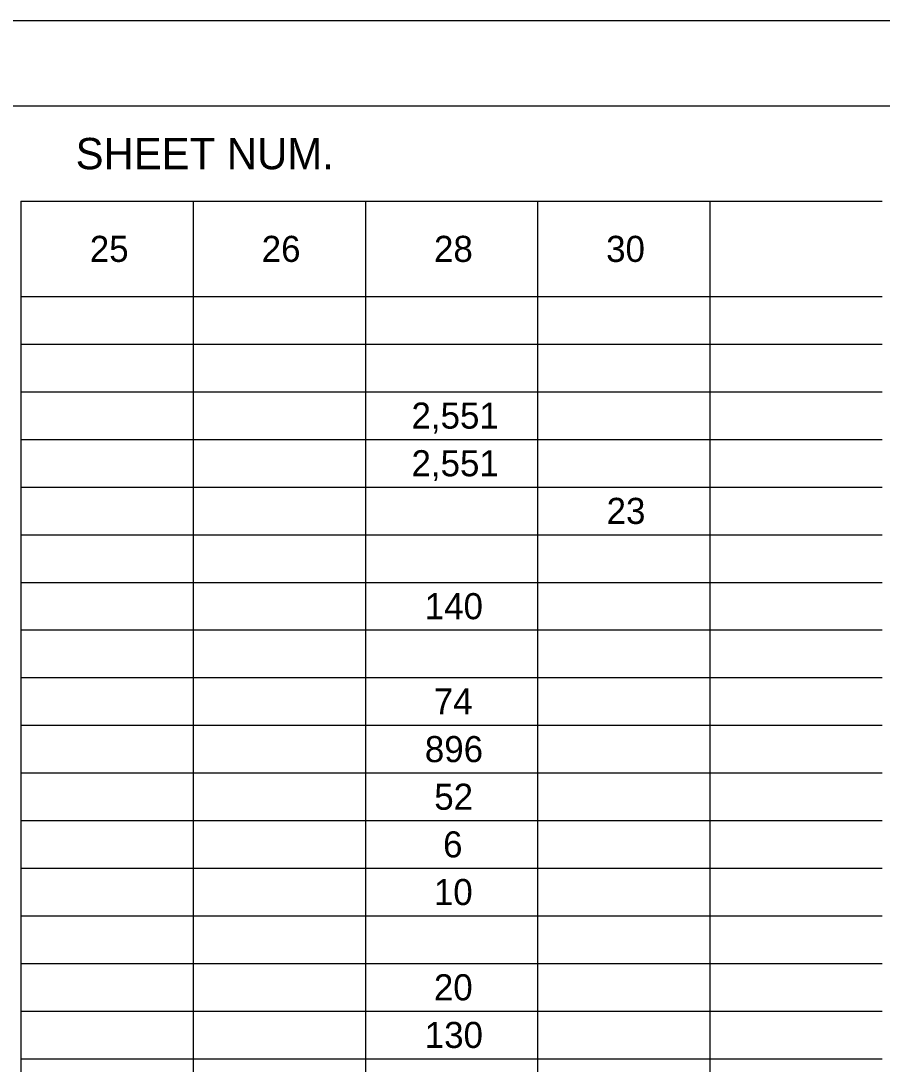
# Model space of a CAD drawing. Extents: x 0 to 34, y 0 to 22.
# Drawn here: x 4.54 to 9.6, y 15.87 to 22 of the extents above; entities that cross this region are included whole.
import ezdxf

# ---------------------------------------------------------------- set-up
doc = ezdxf.new("R2010")
doc.units = 0
for name, color, linetype in [('SH_Border', 7, 'Continuous'), ('SH_Cut_Line', 7, 'Continuous'), ('SH_Text', 7, 'Continuous')]:
    doc.layers.add(name, color=color, linetype=linetype)

msp = doc.modelspace()

# ---------------------------------------------------------------- linework, layer by layer
at = {"layer": 'SH_Border'}
msp.add_lwpolyline([(1.5, 21.5), (33.5, 21.5), (33.5, 0.5), (1.5, 0.5)], close=True, dxfattribs=at)
at = {"layer": 'SH_Cut_Line'}
msp.add_lwpolyline([(0, 0), (34, 0), (34, 22), (0, 22)], close=True, dxfattribs=at)
at = {"layer": 'SH_Text'}
for p, q in [((4.537, 21.5), (5.5494, 21.5)), ((5.5494, 21.5), (6.5617, 21.5)), ((6.5617, 21.5), (7.574, 21.5)), ((7.574, 21.5), (8.5864, 21.5)), ((8.5864, 21.5), (9.5987, 21.5)), ((4.537, 20.94), (5.5494, 20.94)), ((4.537, 20.94), (4.537, 20.66)), ((5.5494, 20.94), (6.5617, 20.94)), ((5.5494, 20.94), (5.5494, 20.66)), ((6.5617, 20.94), (7.574, 20.94)), ((6.5617, 20.94), (6.5617, 20.66)), ((7.574, 20.94), (8.5864, 20.94)), ((7.574, 20.94), (7.574, 20.66)), ((8.5864, 20.94), (9.5987, 20.94)), ((8.5864, 20.94), (8.5864, 20.66)), ((4.537, 20.66), (4.537, 20.38)), ((5.5494, 20.66), (5.5494, 20.38)), ((6.5617, 20.66), (6.5617, 20.38)), ((7.574, 20.66), (7.574, 20.38)), ((8.5864, 20.66), (8.5864, 20.38)), ((4.537, 20.38), (5.5494, 20.38)), ((4.537, 20.38), (4.537, 20.1)), ((5.5494, 20.38), (6.5617, 20.38)), ((5.5494, 20.38), (5.5494, 20.1)), ((6.5617, 20.38), (7.574, 20.38)), ((6.5617, 20.38), (6.5617, 20.1)), ((7.574, 20.38), (8.5864, 20.38)), ((7.574, 20.38), (7.574, 20.1)), ((8.5864, 20.38), (9.5987, 20.38)), ((8.5864, 20.38), (8.5864, 20.1)), ((4.537, 20.1), (5.5494, 20.1)), ((4.537, 20.1), (4.537, 18.7)), ((5.5494, 20.1), (6.5617, 20.1)), ((5.5494, 20.1), (5.5494, 18.7)), ((6.5617, 20.1), (7.574, 20.1)), ((6.5617, 20.1), (6.5617, 18.7)), ((7.574, 20.1), (8.5864, 20.1)), ((7.574, 20.1), (7.574, 18.7)), ((8.5864, 20.1), (9.5987, 20.1)), ((8.5864, 20.1), (8.5864, 18.7)), ((4.537, 19.82), (5.5494, 19.82)), ((5.5494, 19.82), (6.5617, 19.82)), ((6.5617, 19.82), (7.574, 19.82)), ((7.574, 19.82), (8.5864, 19.82)), ((8.5864, 19.82), (9.5987, 19.82)), ((4.537, 19.54), (5.5494, 19.54)), ((5.5494, 19.54), (6.5617, 19.54)), ((6.5617, 19.54), (7.574, 19.54)), ((7.574, 19.54), (8.5864, 19.54)), ((8.5864, 19.54), (9.5987, 19.54)), ((4.537, 19.26), (5.5494, 19.26)), ((5.5494, 19.26), (6.5617, 19.26)), ((6.5617, 19.26), (7.574, 19.26)), ((7.574, 19.26), (8.5864, 19.26)), ((8.5864, 19.26), (9.5987, 19.26)), ((4.537, 18.98), (5.5494, 18.98)), ((5.5494, 18.98), (6.5617, 18.98)), ((6.5617, 18.98), (7.574, 18.98)), ((7.574, 18.98), (8.5864, 18.98)), ((8.5864, 18.98), (9.5987, 18.98)), ((4.537, 18.7), (5.5494, 18.7)), ((4.537, 18.7), (4.537, 18.14)), ((5.5494, 18.7), (6.5617, 18.7)), ((5.5494, 18.7), (5.5494, 18.14)), ((6.5617, 18.7), (7.574, 18.7)), ((6.5617, 18.7), (6.5617, 18.14)), ((7.574, 18.7), (8.5864, 18.7)), ((7.574, 18.7), (7.574, 18.14)), ((8.5864, 18.7), (9.5987, 18.7)), ((8.5864, 18.7), (8.5864, 18.14)), ((4.537, 18.42), (5.5494, 18.42)), ((5.5494, 18.42), (6.5617, 18.42)), ((6.5617, 18.42), (7.574, 18.42)), ((7.574, 18.42), (8.5864, 18.42)), ((8.5864, 18.42), (9.5987, 18.42)), ((4.537, 18.14), (5.5494, 18.14)), ((4.537, 18.14), (4.537, 17.86)), ((5.5494, 18.14), (6.5617, 18.14)), ((5.5494, 18.14), (5.5494, 17.86)), ((6.5617, 18.14), (7.574, 18.14)), ((6.5617, 18.14), (6.5617, 17.86)), ((7.574, 18.14), (8.5864, 18.14)), ((7.574, 18.14), (7.574, 17.86)), ((8.5864, 18.14), (9.5987, 18.14)), ((8.5864, 18.14), (8.5864, 17.86)), ((4.537, 17.86), (5.5494, 17.86)), ((4.537, 17.86), (4.537, 17.58)), ((5.5494, 17.86), (6.5617, 17.86)), ((5.5494, 17.86), (5.5494, 17.58)), ((6.5617, 17.86), (7.574, 17.86)), ((6.5617, 17.86), (6.5617, 17.58)), ((7.574, 17.86), (8.5864, 17.86)), ((7.574, 17.86), (7.574, 17.58)), ((8.5864, 17.86), (9.5987, 17.86)), ((8.5864, 17.86), (8.5864, 17.58)), ((4.537, 17.58), (5.5494, 17.58)), ((4.537, 17.58), (4.537, 17.3)), ((5.5494, 17.58), (6.5617, 17.58)), ((5.5494, 17.58), (5.5494, 17.3)), ((6.5617, 17.58), (7.574, 17.58)), ((6.5617, 17.58), (6.5617, 17.3)), ((7.574, 17.58), (8.5864, 17.58)), ((7.574, 17.58), (7.574, 17.3)), ((8.5864, 17.58), (9.5987, 17.58)), ((8.5864, 17.58), (8.5864, 17.3)), ((4.537, 17.3), (5.5494, 17.3)), ((4.537, 17.3), (4.537, 17.02)), ((5.5494, 17.3), (6.5617, 17.3)), ((5.5494, 17.3), (5.5494, 17.02)), ((6.5617, 17.3), (7.574, 17.3)), ((6.5617, 17.3), (6.5617, 17.02)), ((7.574, 17.3), (8.5864, 17.3)), ((7.574, 17.3), (7.574, 17.02)), ((8.5864, 17.3), (9.5987, 17.3)), ((8.5864, 17.3), (8.5864, 17.02)), ((4.537, 17.02), (5.5494, 17.02)), ((4.537, 17.02), (4.537, 16.74)), ((5.5494, 17.02), (6.5617, 17.02)), ((5.5494, 17.02), (5.5494, 16.74)), ((6.5617, 17.02), (7.574, 17.02)), ((6.5617, 17.02), (6.5617, 16.74)), ((7.574, 17.02), (8.5864, 17.02)), ((7.574, 17.02), (7.574, 16.74)), ((8.5864, 17.02), (9.5987, 17.02)), ((8.5864, 17.02), (8.5864, 16.74)), ((4.537, 16.74), (5.5494, 16.74)), ((4.537, 16.74), (4.537, 16.18)), ((5.5494, 16.74), (6.5617, 16.74)), ((5.5494, 16.74), (5.5494, 16.18)), ((6.5617, 16.74), (7.574, 16.74)), ((6.5617, 16.74), (6.5617, 16.18)), ((7.574, 16.74), (8.5864, 16.74)), ((7.574, 16.74), (7.574, 16.18)), ((8.5864, 16.74), (9.5987, 16.74)), ((8.5864, 16.74), (8.5864, 16.18)), ((4.537, 16.46), (5.5494, 16.46)), ((5.5494, 16.46), (6.5617, 16.46)), ((6.5617, 16.46), (7.574, 16.46)), ((7.574, 16.46), (8.5864, 16.46)), ((8.5864, 16.46), (9.5987, 16.46)), ((4.537, 16.18), (5.5494, 16.18)), ((4.537, 16.18), (4.537, 15.9)), ((5.5494, 16.18), (6.5617, 16.18)), ((5.5494, 16.18), (5.5494, 15.9)), ((6.5617, 16.18), (7.574, 16.18)), ((6.5617, 16.18), (6.5617, 15.9)), ((7.574, 16.18), (8.5864, 16.18)), ((7.574, 16.18), (7.574, 15.9)), ((8.5864, 16.18), (9.5987, 16.18)), ((8.5864, 16.18), (8.5864, 15.9)), ((4.537, 15.9), (5.5494, 15.9)), ((4.537, 15.9), (4.537, 15.62)), ((5.5494, 15.9), (6.5617, 15.9)), ((5.5494, 15.9), (5.5494, 15.62)), ((6.5617, 15.9), (7.574, 15.9)), ((6.5617, 15.9), (6.5617, 15.62)), ((7.574, 15.9), (8.5864, 15.9)), ((7.574, 15.9), (7.574, 15.62)), ((8.5864, 15.9), (9.5987, 15.9)), ((8.5864, 15.9), (8.5864, 15.62))]:
    msp.add_line(p, q, dxfattribs=at)

# ---------------------------------------------------------------- texts
for s, height, p in [('SHEET NUM.', 0.184, (4.8588, 21.128)), ('25', 0.15333, (4.9422, 20.5833)), ('26', 0.15333, (5.9525, 20.5833)), ('28', 0.15333, (6.965, 20.5833)), ('30', 0.15333, (7.9767, 20.5833)), ('2,551', 0.15333, (6.8328, 19.6033)), ('2,551', 0.15333, (6.8328, 19.3233)), ('23', 0.15333, (7.9794, 19.0433)), ('140', 0.15333, (6.9107, 18.4833)), ('74', 0.15333, (6.9637, 17.9233)), ('896', 0.15333, (6.9112, 17.6433)), ('52', 0.15333, (6.9665, 17.3633)), ('6', 0.1533, (7.0184, 17.0833)), ('10', 0.15333, (6.9643, 16.8033)), ('20', 0.15333, (6.9643, 16.2433)), ('130', 0.15333, (6.9107, 15.9633))]:
    msp.add_text(s, height=height, dxfattribs=at).set_placement(p)

doc.saveas('drawing.dxf')
